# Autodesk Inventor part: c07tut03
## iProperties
Shininess: 77.0
Length Units: 11269
Angle Units: 11279
Time Units: 11290
Mass Units: 11283
Length Display Precision: 3
Angle Display Precision: 2
Created: 2002-01
Part Number: c07tut03
Document SubType Name: Modeling
Designer: ***
Density: 1 g/cm^3
Density: 0.0
Volumn: 0.0
Area: 0.0
PropertySet Name: Model Information
Control State: 0
Master: False
Checked Out: False
Author: ***
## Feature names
1. Extrusion1
2. Fillet1
3. Extrusion2
